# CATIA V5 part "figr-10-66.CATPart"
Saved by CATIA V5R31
Part number: Part1
Bounding box of the stored display mesh (mm): x -80.563 to 63.541, y -72 to 69, z -55 to 56
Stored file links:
  D:\PROJECTS\Project 2021\US EDITION\CATIA V5 6R 2021\Resources\Part Files\c10_catia_v5_6r2021_prt\c10_catia_v5_6r2021_prt\figr-10-66.CATPart
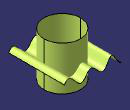
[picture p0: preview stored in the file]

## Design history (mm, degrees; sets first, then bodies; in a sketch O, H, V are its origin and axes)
Set1
  Sketch1 on xy-plane, origin (0, 0, 0), H (-1, 0, 0), V (0, -1, 0)
    circle A1 centre (0, 0) radius 45.985
  Extrude1: Element1 Sketch1, Lim1 56, Lim2 55, Direction xy-plane
  Sketch2 on zx-plane, origin (0, 0, 0), H (1, 0, 0), V (0, 0, -1)
    spline S1 through (-80.5635, 24.8913) (-73.6025, 19.8803) (-54.8525, -3.3629) (-35.1982, 19.8803) (-2.6271, -1.6506) (16.6996, 17.2854) (52.4104, -6.7877) (63.5409, 1.5862)
  Extrude2: Element1 Sketch2, Lim1 72, Lim2 69, Direction Sketch1.V
Body1 (main body)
